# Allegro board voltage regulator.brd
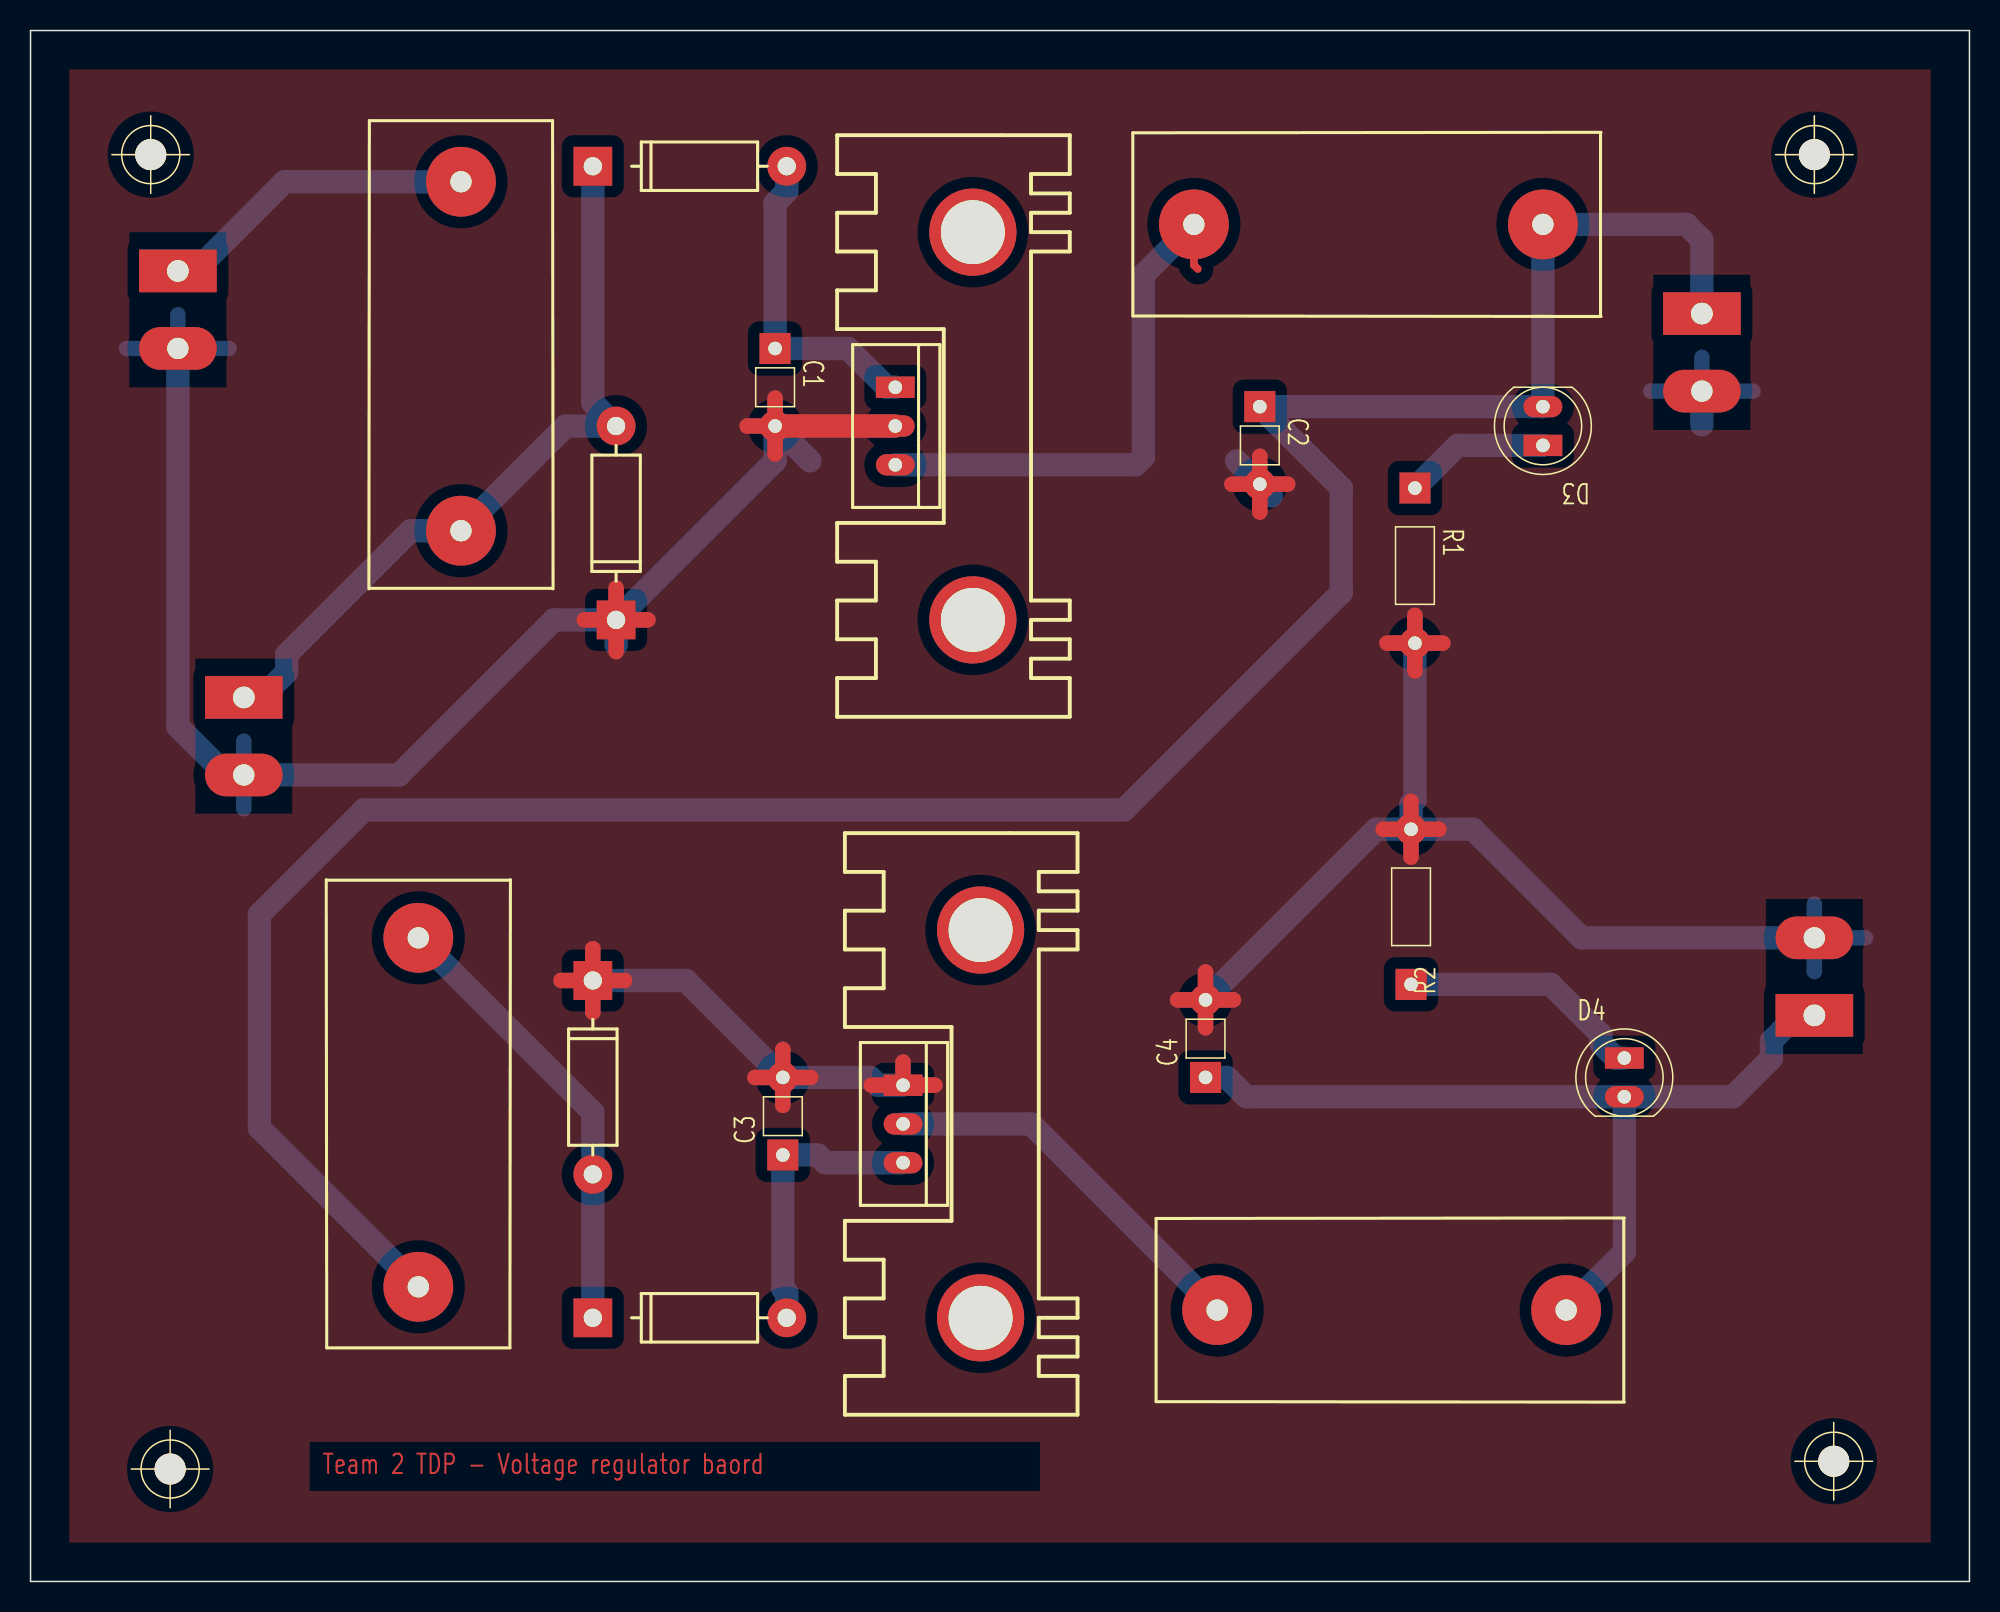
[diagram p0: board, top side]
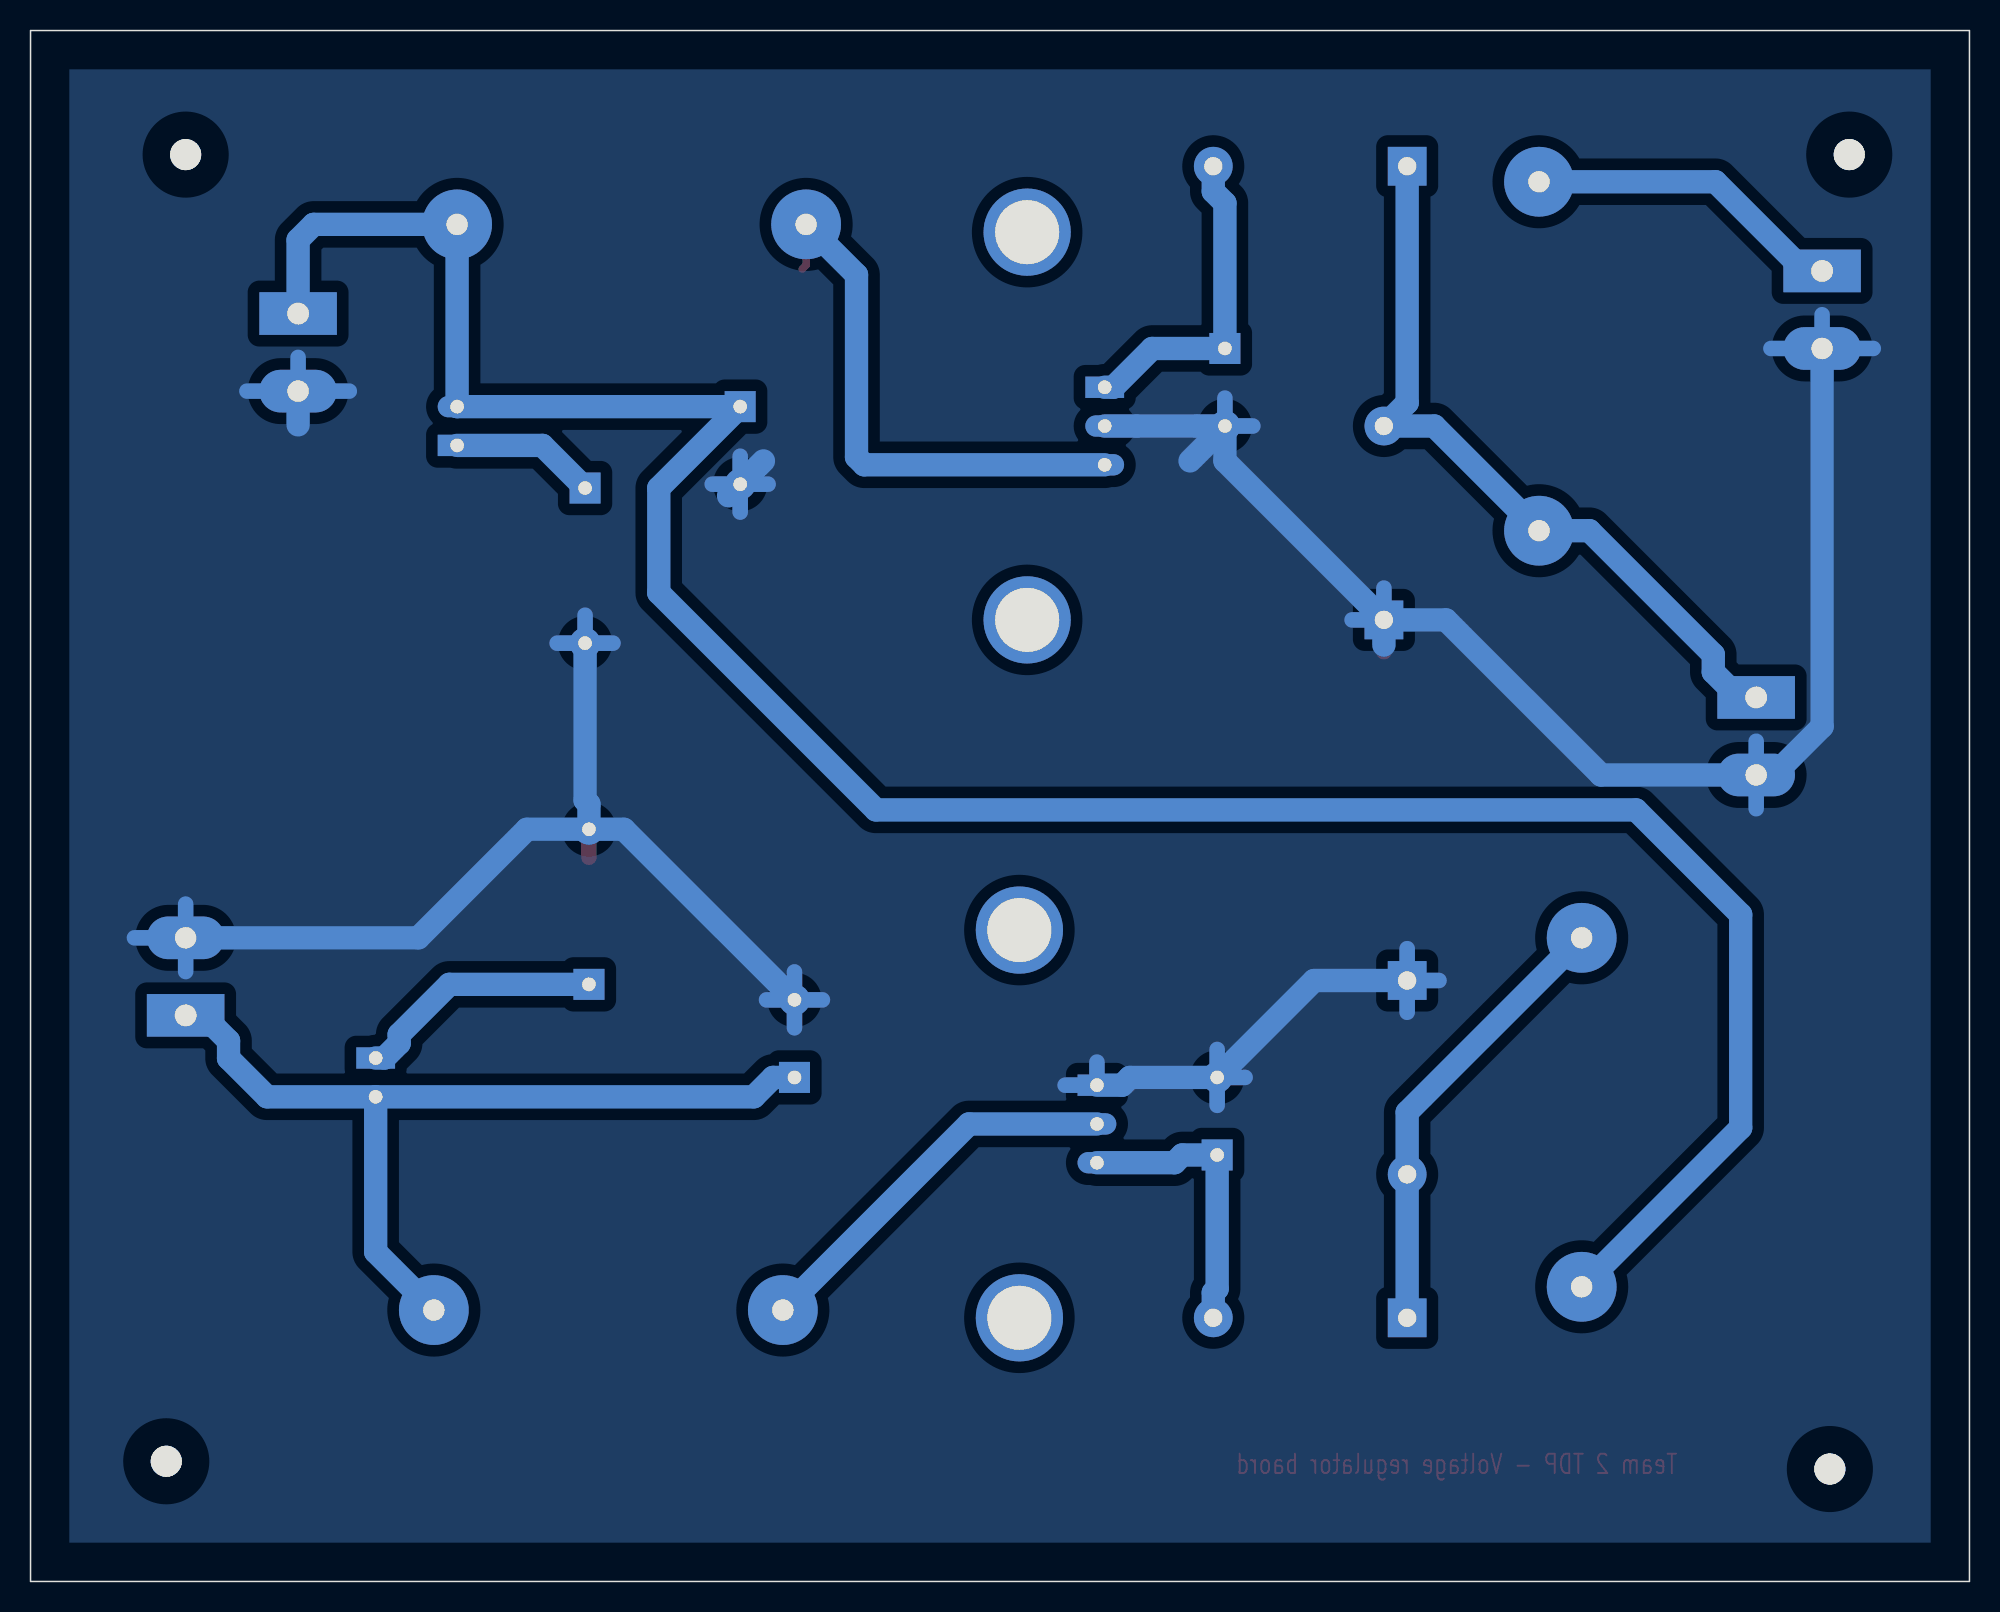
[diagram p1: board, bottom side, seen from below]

Outline 127 x 101.6 mm; copper layers: TOP, BOTTOM. Coordinates in mm from the lower left corner of the outline.
Outline path: rectangle 0,0 127,101.6

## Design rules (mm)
constraint set DEFAULT: min track width 0.508
nets with their own width: min track width 1.016; nets GND N00482 N00486

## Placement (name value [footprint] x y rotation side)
C1  470n  [GU-RC200]  48.77 80.77 270 top
C2  220n  [GU-RC200]  80.52 76.96 270 top
C3  100n  [GU-RC200]  49.28 27.94 90 top
C4  10u  [GU-RC200]  76.96 33.02 90 top
D1  DIODE  [GU-1N4001]  36.83 92.71 0 top
D2  DIODE  [GU-1N4001]  36.83 17.27 0 top
D3  LED  [GU-LED5MM]  99.06 74.42 180 top
D4  LED  [GU-LED5MM]  104.39 34.29 0 top
D5  15V  [GU-1N4001]  36.83 39.37 270 top
D6  15V  [GU-1N4001]  38.35 62.99 90 top
F1  FUSEHOLDER  [GU-FUSEHOLDER-20MM]  28.19 91.69 270 top
F2  FUSEHOLDER  [GU-FUSEHOLDER-20MM]  76.2 88.9 0 top
F3  FUSEHOLDER  [GU-FUSEHOLDER-20MM]  25.4 19.3 90 top
F4  FUSEHOLDER  [GU-FUSEHOLDER-20MM]  77.72 17.78 0 top
J1  CON2  [GU-TERMINAL2-200]  13.97 57.91 0 top
J2  CON2  [GU-TERMINAL2-200]  9.65 85.85 0 top
J3  CON2  [GU-TERMINAL2-200]  109.47 83.06 0 top
J5  CON2  [GU-TERMINAL2-200]  116.84 37.08 180 top
NOREF  -  [unnamed]  7.87 93.47 0 top
NOREF#2  -  [unnamed]  118.11 7.87 0 top
NOREF#3  -  [unnamed]  9.14 7.37 0 top
NOREF#4  -  [unnamed]  116.84 93.47 0 top
R1  430  [GU-RC400]  90.68 71.63 270 top
R2  430  [GU-RC400]  90.42 39.12 90 top
U1  L7805/TO220  [GU-TO220AB-HSINK]  56.64 78.23 270 top
U2  LD1117/DD  [GU-TO220AB-HSINK]  57.15 32.51 270 top

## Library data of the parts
C1-C4 = CAP NP
D1 D2 = DIODE
D3 D4 = LED
D5 D6 = DIODE ZENER
F1-F4 = FUSEHOLDER
J1-J3 J5 = CON2: User Part Number: TERMINAL2-200
R1 R2 = R
U1 = L7805/TO220_1
U2 = LD1117/DD_0

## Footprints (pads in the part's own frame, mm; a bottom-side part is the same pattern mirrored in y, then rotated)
GU-1N4001
  round 2.54 hole 1.194: 1(12.7,0)
  rect 2.54x2.54 hole 1.194: 2(0,0)
GU-FUSEHOLDER-20MM
  round 4.572 hole 1.397: 1(0,0) 2(22.86,0)
GU-LED5MM
  rect 2.54x1.397 hole 0.889: 1(0,0)
  oval 2.54x1.397 hole 0.889: 2(0,-2.54)
GU-RC200
  rect 2.032x2.032 hole 0.889: 1(0,0)
  round 2.032 hole 0.889: 2(5.08,0)
GU-RC400
  rect 2.032x2.032 hole 0.889: 1(0,0)
  round 2.032 hole 0.889: 2(10.16,0)
GU-TERMINAL2-200
  rect 5.08x2.794 hole 1.422: 1(0,0)
  oval 5.08x2.794 hole 1.397: 2(0,-5.08)
GU-TO220AB-HSINK
  round 5.715 hole 4.191 unplated: (-10.16,5.08) (15.24,5.08)
  rect 1.397x2.54 hole 0.889: 1(0,0)
  oval 1.397x2.54 hole 0.889: 2(2.54,0) 3(5.08,0)
unnamed
  round 2.032 hole 3.962 unplated: (0,0)

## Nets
GND: C1.2 C2.2 C3.2 C4.2 D5.2 D6.2 J1.2 J2.2 J3.2 J5.2 R1.2 R2.2 U1.2 U2.1
N00482: F1.1 J2.1
N00486: D1.2 D6.1(CATHODE) F1.2 J1.1
N00778: F2.1 U1.3(VOUT)
N00897: C2.1 D3.2 F2.2 F3.1 J3.1
N01243: C1.1 D1.1(K) U1.1
N01262: D3.1(CATHODE) R1.1
N01283: D2.2 D5.1(CATHODE) F3.2
N01420: C3.1 D2.1(K) U2.3
N01440: F4.1 U2.2(VOUT)
N01444: C4.1 D4.2 F4.2 J5.1
N01448: D4.1(CATHODE) R2.1

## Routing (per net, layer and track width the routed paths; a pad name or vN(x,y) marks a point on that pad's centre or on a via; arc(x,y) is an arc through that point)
GND: length 322.7
  TOP w1.016: U2.1 59.23,32.51 ; U2.1 57.15,34.02 ; U2.1 55.07,32.51 ; 90.68,59.64 R1.2 ; R1.2 88.85,61.47 ; R1.2 92.51,61.47 ; R1.2 90.68,63.3 ; 34.75,39.37 D5.2 ; D5.2 36.83,37.29 ; D5.2 36.83,41.45 ; D5.2 38.91,39.37 ; 47.45,33.02 C3.2 ; C3.2 51.11,33.02 ; C3.2 49.28,31.19 ; C3.2 49.28,34.85 ; 46.94,75.69 C1.2 ; C1.2 48.77,73.86 ; C1.2 48.77,77.52 ; 38.35,60.91 D6.2 ; D6.2 38.35,65.08 ; D6.2 40.44,62.99 ; D6.2 36.27,62.99 ; C2.2 82.35,71.88 ; C2.2 80.52,73.71 ; C2.2 80.52,70.05 ; C2.2 78.69,71.88 ; 90.42,47.45 R2.2 ; R2.2 90.42,51.11 ; R2.2 88.59,49.28 ; R2.2 92.25,49.28 ; 76.96,36.27 C4.2 ; C4.2 78.79,38.1 ; C4.2 76.96,39.93 ; C4.2 75.13,38.1
  TOP w1.524: C1.2 U1.2
  BOTTOM w1.016: 76.96,36.27 C4.2 ; C4.2 75.13,38.1 ; C4.2 76.96,39.93 ; C4.2 78.79,38.1 ; 88.85,61.47 R1.2 ; R1.2 92.51,61.47 ; R1.2 90.68,63.3 ; 6.3,80.77 J2.2 ; J2.2 13.01,80.77 ; J2.2 9.65,82.98 ; 46.94,75.69 C1.2 48.77,77.52 ; J5.2 116.84,44.37 ; J5.2 120.19,42.16 ; J5.2 116.84,39.95 ; J3.2 112.83,77.98 ; J3.2 106.12,77.98 ; J3.2 109.47,80.19 ; 13.97,55.04 J1.2 13.97,50.62 ; 59.23,32.51 U2.1 57.15,34.02 ; 78.69,71.88 C2.2 ; C2.2 80.52,70.05 ; C2.2 80.52,73.71 ; C2.2 82.35,71.88 ; 49.28,31.19 C3.2 ; C3.2 49.28,34.85 ; C3.2 47.45,33.02 ; 36.83,37.29 D5.2 ; D5.2 36.83,41.45 ; D5.2 34.75,39.37 ; 40.44,62.99 D6.2 38.35,65.08
  BOTTOM w1.524: D5.2 42.93,39.37 C3.2 54.99,33.02 55.5,32.51 U2.1 ; 78.99,73.41 C2.2 81.28,71.12 ; J5.2 101.6,42.16 94.49,49.28 R2.2 ; C1.2 U1.2 ; C1.2 48.77,73.41 D6.2 ; C1.2 51.05,73.41 ; R2.2 88.14,49.28 C4.2 ; R2.2 90.42,50.93 90.68,51.18 R1.2 ; J2.2 9.65,56.01 12.83,52.83 J1.2 24.13,52.83 34.29,62.99 D6.2 ; D6.2 38.35,61.34 ; J3.2 109.47,75.77
N00482: length 21
  BOTTOM w1.524: F1.1 16.64,91.69 10.8,85.85 J2.1
N00486: length 50.1
  BOTTOM w1.524: D1.2 36.83,77.22 D6.1 35.05,75.69 F1.2 24.89,68.83 16.78,60.72 16.78,59.58 15.11,57.91 J1.1
N00778: length 36.1
  TOP w0.508: 76.45,85.98 76.2,86.23 F2.1
  BOTTOM w1.524: F2.1 72.9,85.6 72.9,73.66 72.39,73.15 U1.3
N00897: length 168.8
  BOTTOM w1.524: F3.1 14.99,29.72 14.99,43.69 21.84,50.55 71.63,50.55 85.85,64.77 85.85,71.63 C2.1 D3.2 F2.2 108.46,88.9 109.47,87.88 J3.1
N01243: length 21.2
  BOTTOM w1.524: D1.1 49.53,91.06 48.77,90.3 C1.1 53.53,80.77 56.07,78.23 U1.1
N01262: length 9.5
  BOTTOM w1.524: D3.1 93.47,74.42 R1.1
N01283: length 29.6
  BOTTOM w1.524: D2.2 D5.1 36.83,30.73 F3.2
N01420: length 18.9
  BOTTOM w1.524: D2.1 49.53,18.92 49.28,19.18 C3.1 51.56,27.94 52.07,27.43 U2.3
N01440: length 25.6
  BOTTOM w1.524: F4.1 65.53,29.97 U2.2
N01444: length 58.8
  BOTTOM w1.524: D4.2 79.63,31.75 78.36,33.02 C4.1 ; D4.2 104.39,21.59 F4.2 ; D4.2 111.51,31.75 114.03,34.27 114.03,35.42 115.7,37.08 J5.1
N01448: length 16.3
  BOTTOM w1.524: D4.1 103.82,34.29 102.85,35.26 102.85,35.83 99.57,39.12 R2.1

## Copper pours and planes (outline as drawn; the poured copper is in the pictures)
GND on TOP, BOTTOM: 2.54,99.06 124.46,99.06 124.46,2.54 2.54,2.54

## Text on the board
TOP: Team 2 TDP - Voltage regulator baord
